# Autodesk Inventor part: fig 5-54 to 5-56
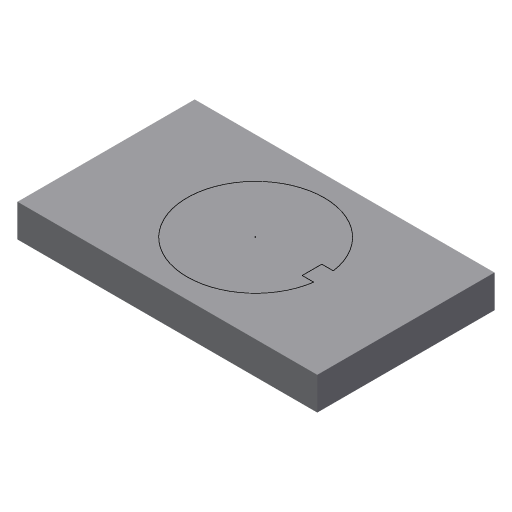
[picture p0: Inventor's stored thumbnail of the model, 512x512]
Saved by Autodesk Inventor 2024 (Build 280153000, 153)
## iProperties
Created: 2005-12
Part Number: fig 5-54 to 5-56
Document SubType Name: Modeling
Designer: CADCIM
Density: 1 g/cm^3
Material: Generic
Appearance: Default
Author: CADCIM
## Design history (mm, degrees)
sketch "Sketch1"
  geometry: L1 (-47.674, -20.831)-(44.057, -20.831); L2 (44.057, -20.831)-(44.057, 33.398); L3 (44.057, 33.398)-(-47.674, 33.398); L4 (-47.674, 33.398)-(-47.674, -20.831)
  constraints: 8 end point, 2 parallel, 1 horizontal, 1 perpendicular
extrude "Extrusion1" new body sketch "Sketch1" distance "d0" = 10; taper "d1" = 0 deg
sketch "Sketch2"
  geometry: L1 (15.359, 9.199)-(18.885, 9.199); L2 (18.885, 3.199)-(15.359, 3.199); L3 (15.359, 3.199)-(15.359, 9.199); A1 r 20.978 centre (-1.877, 6.199) between (18.885, 9.199) and (18.885, 3.199)
  constraints: 6 end point, 2 parallel, 2 point on circle, 1 centre point, 1 horizontal, 1 vertical
body "Solid1"
